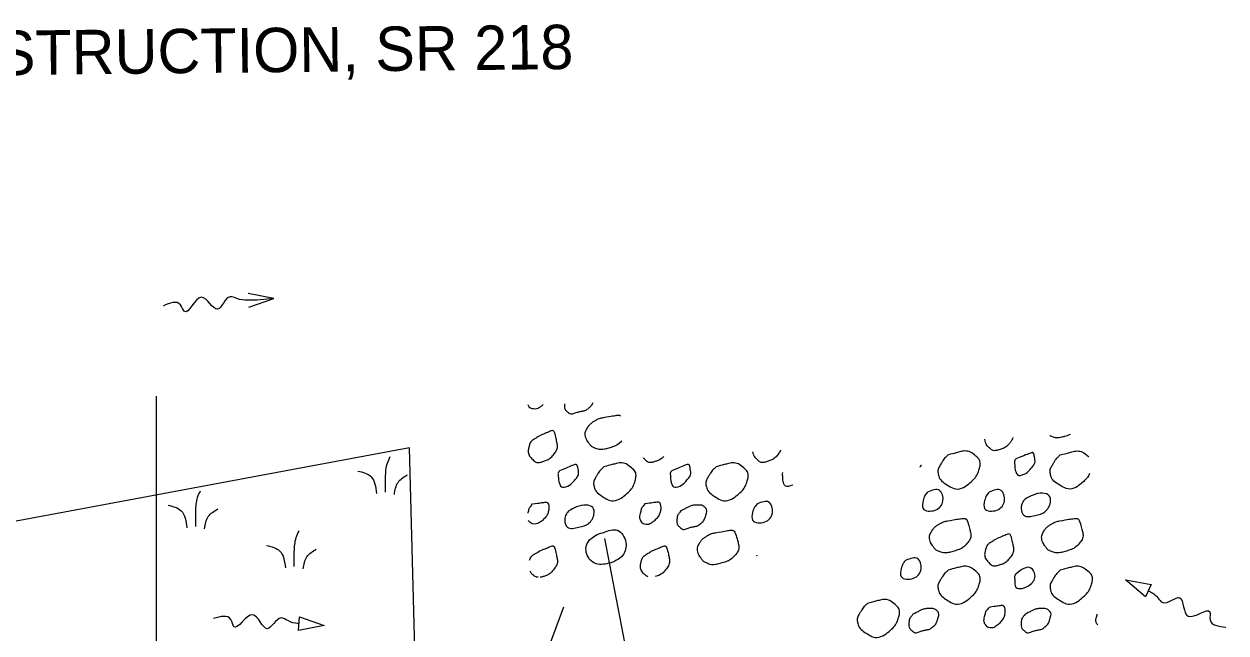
# Model space of a CAD drawing. Extents: x 0 to 3369, y -440 to 440.
# Drawn here: x 466.9 to 542.6, y 270.9 to 309.3 of the extents above; entities that cross this region are included whole.
import ezdxf

# ---------------------------------------------------------------- set-up
doc = ezdxf.new("R2010")
doc.units = 0
for name, color, linetype in [('GE_P_Alignment', 7, 'Continuous'), ('GE_P_Alignment_100_Stations', 7, 'Continuous'), ('MT_P_Work_Area', 7, 'Continuous'), ('PF_P_Grade_Line', 7, 'Continuous'), ('PV_P_EOP', 7, 'Continuous'), ('PV_P_Shoulder', 7, 'Continuous')]:
    doc.layers.add(name, color=color, linetype=linetype)

msp = doc.modelspace()

# ---------------------------------------------------------------- linework, layer by layer
at = {"layer": 'GE_P_Alignment'}
for points, degree in [([(499.586, 285.35), (499.531, 285.297), (499.473, 285.247), (499.415, 285.202), (499.205, 285.042), (498.763, 285.069), (498.642, 285.316), (498.641, 285.316), (498.641, 285.317), (498.641, 285.318)], 3), ([(502.709, 285.462), (502.654, 285.334), (502.575, 285.211), (502.448, 285.106), (502.248, 284.94), (502.037, 284.916), (501.822, 284.866), (501.596, 284.813), (501.339, 284.68), (501.118, 284.877), (500.973, 285.008), (500.943, 285.16), (500.947, 285.309), (500.948, 285.338), (500.949, 285.367), (500.951, 285.398)], 3), ([(504.541, 283.036), (504.291, 282.79), (504.016, 282.687), (503.713, 282.597), (503.431, 282.514), (503.115, 282.484), (502.833, 282.602), (502.663, 282.674), (502.539, 282.799), (502.435, 282.959), (502.262, 283.227), (502.211, 283.596), (502.362, 283.849), (502.462, 284.017), (502.598, 284.165), (502.772, 284.276), (502.919, 284.37), (503.06, 284.458), (503.223, 284.492), (503.278, 284.504), (503.333, 284.516), (503.388, 284.527)], 3), ([(503.372, 284.524), (503.674, 284.576), (503.977, 284.634), (504.28, 284.676), (504.345, 284.685), (504.403, 284.668), (504.454, 284.633)], 3), ([(499.332, 283.359), (499.566, 283.46), (499.801, 283.56), (500.035, 283.661), (500.278, 283.765), (500.397, 283.232), (500.45, 282.984), (500.507, 282.722), (500.439, 282.428), (500.227, 282.174), (500.027, 281.935), (499.8, 281.822), (499.56, 281.749), (499.368, 281.691), (499.126, 281.682), (498.938, 281.867), (498.711, 282.092), (498.626, 282.357), (498.672, 282.586), (498.708, 282.768), (498.793, 283.008), (498.963, 283.121), (499.086, 283.202), (499.209, 283.279), (499.332, 283.359)], 3), ([(532.818, 283.458), (532.71, 283.413), (532.598, 283.376), (532.482, 283.342), (532.199, 283.259), (531.883, 283.229), (531.602, 283.347), (531.573, 283.359), (531.546, 283.373), (531.52, 283.388)], 3), ([(529.189, 283.261), (529.15, 283.143), (529.085, 283.027), (528.995, 282.919), (528.796, 282.68), (528.568, 282.566), (528.328, 282.494), (528.136, 282.436), (527.895, 282.426), (527.707, 282.612), (527.532, 282.785), (527.442, 282.98), (527.429, 283.165)], 3), ([(507.195, 282.063), (507.022, 281.898), (506.831, 281.809), (506.632, 281.749), (506.44, 281.691), (506.198, 281.682), (506.01, 281.867), (505.969, 281.908), (505.932, 281.95), (505.901, 281.993)], 3), ([(514.545, 282.464), (514.505, 282.364), (514.447, 282.267), (514.37, 282.174), (514.171, 281.935), (513.943, 281.822), (513.703, 281.749), (513.512, 281.691), (513.27, 281.682), (513.082, 281.867), (512.923, 282.024), (512.834, 282.2), (512.81, 282.369)], 3), ([(525.11, 282.166), (525.347, 282.229), (525.584, 282.291), (525.822, 282.352), (526.168, 282.442), (526.517, 282.379), (526.863, 282.089), (527.132, 281.864), (527.149, 281.532), (527.078, 281.284), (526.988, 280.971), (526.79, 280.673), (526.487, 280.414), (526.107, 280.089), (525.579, 279.962), (525.19, 280.192), (524.875, 280.379), (524.542, 280.659), (524.482, 280.989), (524.444, 281.195), (524.551, 281.434), (524.672, 281.626), (524.758, 281.762), (524.834, 281.901), (524.948, 282.011), (525.002, 282.062), (525.056, 282.114), (525.11, 282.166)], 3), ([(529.383, 281.914), (529.7, 282.042), (530.017, 282.178), (530.333, 282.299), (530.489, 282.358), (530.571, 282.011), (530.585, 281.862), (530.604, 281.663), (530.451, 281.455), (530.287, 281.257), (530.063, 280.989), (529.502, 280.794), (529.387, 281.089), (529.325, 281.246), (529.315, 281.407), (529.308, 281.569), (529.305, 281.649), (529.275, 281.739), (529.317, 281.811), (529.338, 281.847), (529.361, 281.879), (529.383, 281.914)], 3), ([(534.03, 280.987), (533.922, 280.783), (533.764, 280.59), (533.558, 280.414), (533.178, 280.089), (532.65, 279.962), (532.262, 280.192), (531.946, 280.379), (531.614, 280.659), (531.553, 280.989), (531.515, 281.195), (531.622, 281.434), (531.743, 281.626), (531.829, 281.762), (531.906, 281.901), (532.02, 282.011), (532.074, 282.062), (532.127, 282.114), (532.182, 282.166)], 3), ([(532.182, 282.166), (532.419, 282.229), (532.656, 282.291), (532.893, 282.352), (533.24, 282.442), (533.588, 282.379), (533.935, 282.089), (533.948, 282.078), (533.96, 282.067), (533.971, 282.056)], 3), ([(500.615, 281.169), (500.932, 281.297), (501.248, 281.434), (501.565, 281.554), (501.721, 281.613), (501.803, 281.266), (501.817, 281.117), (501.836, 280.918), (501.683, 280.71), (501.518, 280.512), (501.295, 280.244), (500.734, 280.049), (500.618, 280.344), (500.557, 280.501), (500.547, 280.662), (500.54, 280.824), (500.537, 280.905), (500.507, 280.994), (500.548, 281.066), (500.57, 281.102), (500.593, 281.134), (500.615, 281.169)], 3), ([(503.413, 281.421), (503.65, 281.484), (503.888, 281.546), (504.125, 281.607), (504.472, 281.697), (504.82, 281.634), (505.167, 281.344), (505.435, 281.12), (505.453, 280.787), (505.382, 280.539), (505.292, 280.226), (505.094, 279.929), (504.79, 279.669), (504.41, 279.345), (503.882, 279.217), (503.493, 279.447), (503.178, 279.634), (502.846, 279.914), (502.785, 280.244), (502.747, 280.45), (502.854, 280.689), (502.975, 280.881), (503.061, 281.018), (503.138, 281.156), (503.252, 281.266), (503.306, 281.318), (503.359, 281.369), (503.413, 281.421)], 3), ([(507.687, 281.169), (508.003, 281.297), (508.32, 281.434), (508.637, 281.554), (508.792, 281.613), (508.874, 281.266), (508.888, 281.117), (508.907, 280.918), (508.754, 280.71), (508.59, 280.512), (508.367, 280.244), (507.806, 280.049), (507.69, 280.344), (507.629, 280.501), (507.618, 280.662), (507.612, 280.824), (507.608, 280.905), (507.578, 280.994), (507.62, 281.066), (507.641, 281.102), (507.665, 281.134), (507.687, 281.169)], 3), ([(510.485, 281.421), (510.722, 281.484), (510.96, 281.546), (511.197, 281.607), (511.543, 281.697), (511.892, 281.634), (512.238, 281.344), (512.507, 281.12), (512.525, 280.787), (512.453, 280.539), (512.364, 280.226), (512.166, 279.929), (511.862, 279.669), (511.482, 279.345), (510.954, 279.217), (510.565, 279.447), (510.25, 279.634), (509.918, 279.914), (509.857, 280.244), (509.819, 280.45), (509.926, 280.689), (510.047, 280.881), (510.133, 281.018), (510.21, 281.156), (510.323, 281.266), (510.377, 281.318), (510.431, 281.369), (510.485, 281.421)], 3), ([(523.415, 281.528), (523.388, 281.483), (523.358, 281.439), (523.325, 281.395)], 2), ([(515.318, 280.267), (515.087, 280.167), (514.835, 280.157), (514.762, 280.344), (514.7, 280.501), (514.69, 280.662), (514.683, 280.824), (514.68, 280.9), (514.654, 280.983), (514.685, 281.052)], 3), ([(498.635, 278.501), (498.639, 278.516), (498.643, 278.532), (498.647, 278.547), (498.677, 278.656), (498.692, 278.782), (498.763, 278.873), (498.817, 278.941), (498.87, 279.008), (498.923, 279.075)], 3), ([(498.923, 279.075), (499.178, 279.112), (499.432, 279.152), (499.687, 279.187), (499.914, 279.217), (499.967, 278.726), (499.895, 278.53), (499.816, 278.313), (499.619, 278.097), (499.415, 277.942), (499.21, 277.784), (498.782, 277.807), (498.65, 278.039)], 3), ([(505.995, 279.075), (506.25, 279.112), (506.504, 279.152), (506.758, 279.187), (506.986, 279.217), (507.039, 278.726), (506.967, 278.53), (506.888, 278.313), (506.69, 278.097), (506.487, 277.942), (506.277, 277.781), (505.835, 277.808), (505.713, 278.055), (505.637, 278.21), (505.675, 278.391), (505.718, 278.547), (505.749, 278.656), (505.763, 278.782), (505.835, 278.873), (505.888, 278.941), (505.942, 279.008), (505.995, 279.075)], 3), ([(508.27, 278.642), (508.437, 278.725), (508.603, 278.808), (508.77, 278.892), (508.953, 278.983), (509.172, 279.001), (509.372, 279.007), (509.519, 279.011), (509.661, 278.976), (509.793, 278.845), (509.915, 278.725), (509.897, 278.565), (509.862, 278.438), (509.803, 278.228), (509.724, 278.015), (509.52, 277.845), (509.32, 277.679), (509.108, 277.655), (508.893, 277.605), (508.668, 277.552), (508.41, 277.419), (508.19, 277.617), (508.045, 277.747), (508.014, 277.899), (508.018, 278.048), (508.022, 278.181), (508.038, 278.337), (508.122, 278.448), (508.171, 278.514), (508.22, 278.577), (508.27, 278.642)], 3), ([(525.068, 278.008), (525.371, 278.06), (525.674, 278.117), (525.977, 278.16), (526.279, 278.202), (526.419, 277.683), (526.495, 277.4), (526.564, 277.142), (526.519, 276.827), (526.302, 276.586), (526.035, 276.291), (525.739, 276.178), (525.41, 276.081), (525.127, 275.998), (524.811, 275.968), (524.53, 276.086), (524.359, 276.158), (524.235, 276.283), (524.132, 276.443), (523.959, 276.711), (523.907, 277.08), (524.058, 277.333), (524.158, 277.501), (524.294, 277.649), (524.468, 277.76), (524.616, 277.853), (524.757, 277.942), (524.92, 277.976), (524.975, 277.988), (525.03, 278), (525.085, 278.011)], 3), ([(532.14, 278.008), (532.442, 278.06), (532.746, 278.117), (533.048, 278.16), (533.351, 278.202), (533.491, 277.683), (533.567, 277.4), (533.635, 277.142), (533.591, 276.827), (533.373, 276.586), (533.107, 276.291), (532.81, 276.178), (532.482, 276.081), (532.199, 275.998), (531.883, 275.968), (531.602, 276.086), (531.431, 276.158), (531.307, 276.283), (531.203, 276.443), (531.03, 276.711), (530.979, 277.08), (531.13, 277.333), (531.23, 277.501), (531.366, 277.649), (531.54, 277.76), (531.687, 277.853), (531.828, 277.942), (531.992, 277.976), (532.047, 277.988), (532.102, 278), (532.157, 278.011)], 3), ([(510.443, 277.263), (510.746, 277.315), (511.049, 277.373), (511.352, 277.415), (511.654, 277.457), (511.794, 276.938), (511.87, 276.655), (511.939, 276.397), (511.894, 276.082), (511.677, 275.842), (511.41, 275.546), (511.114, 275.433), (510.785, 275.337), (510.503, 275.253), (510.186, 275.223), (509.905, 275.342), (509.734, 275.413), (509.61, 275.538), (509.507, 275.698), (509.334, 275.966), (509.282, 276.335), (509.433, 276.588), (509.533, 276.756), (509.669, 276.904), (509.843, 277.015), (509.991, 277.109), (510.132, 277.197), (510.295, 277.232), (510.35, 277.243), (510.405, 277.255), (510.46, 277.267)], 3), ([(528.1, 276.843), (528.334, 276.943), (528.569, 277.044), (528.803, 277.145), (529.046, 277.249), (529.165, 276.715), (529.218, 276.468), (529.275, 276.206), (529.207, 275.912), (528.995, 275.658), (528.796, 275.419), (528.568, 275.305), (528.328, 275.233), (528.136, 275.175), (527.895, 275.166), (527.707, 275.351), (527.479, 275.576), (527.394, 275.841), (527.44, 276.07), (527.476, 276.252), (527.561, 276.491), (527.732, 276.605), (527.854, 276.686), (527.977, 276.763), (528.1, 276.843)], 3), ([(498.733, 275.539), (498.782, 275.665), (498.855, 275.788), (498.963, 275.86), (499.086, 275.941), (499.209, 276.018), (499.332, 276.098)], 3), ([(499.332, 276.098), (499.566, 276.199), (499.801, 276.299), (500.035, 276.4), (500.278, 276.504), (500.397, 275.971), (500.45, 275.723), (500.507, 275.461), (500.439, 275.167), (500.227, 274.913), (500.027, 274.674), (499.8, 274.561), (499.56, 274.488), (499.506, 274.472), (499.448, 274.459), (499.389, 274.454)], 3), ([(506.185, 274.49), (506.124, 274.515), (506.065, 274.553), (506.01, 274.607), (505.783, 274.831), (505.698, 275.096), (505.743, 275.325), (505.78, 275.507), (505.865, 275.747), (506.035, 275.86), (506.158, 275.941), (506.281, 276.018), (506.403, 276.098)], 3), ([(506.403, 276.098), (506.638, 276.199), (506.872, 276.299), (507.107, 276.4), (507.35, 276.504), (507.468, 275.971), (507.522, 275.723), (507.578, 275.461), (507.51, 275.167), (507.298, 274.913), (507.103, 274.679), (506.881, 274.566), (506.647, 274.493)], 3), ([(513.045, 275.81), (513.057, 275.821), (513.069, 275.832), (513.082, 275.842)], 2), ([(525.11, 274.905), (525.347, 274.968), (525.584, 275.03), (525.822, 275.091), (526.168, 275.181), (526.517, 275.118), (526.863, 274.828), (527.132, 274.603), (527.149, 274.271), (527.078, 274.023), (526.988, 273.71), (526.79, 273.412), (526.487, 273.153), (526.107, 272.828), (525.579, 272.701), (525.19, 272.931), (524.875, 273.118), (524.542, 273.398), (524.482, 273.728), (524.444, 273.934), (524.551, 274.173), (524.672, 274.365), (524.758, 274.501), (524.834, 274.64), (524.948, 274.75), (525.002, 274.802), (525.056, 274.853), (525.11, 274.905)], 3), ([(532.182, 274.905), (532.419, 274.968), (532.656, 275.03), (532.893, 275.091), (533.24, 275.181), (533.588, 275.118), (533.935, 274.828), (534.204, 274.603), (534.221, 274.271), (534.15, 274.023), (534.06, 273.71), (533.862, 273.412), (533.558, 273.153), (533.178, 272.828), (532.65, 272.701), (532.262, 272.931), (531.946, 273.118), (531.614, 273.398), (531.553, 273.728), (531.515, 273.934), (531.622, 274.173), (531.743, 274.365), (531.829, 274.501), (531.906, 274.64), (532.02, 274.75), (532.074, 274.802), (532.127, 274.853), (532.182, 274.905)], 3), ([(499.272, 274.453), (499.156, 274.463), (499.039, 274.507), (498.938, 274.607), (498.861, 274.683), (498.801, 274.763), (498.756, 274.846)], 3), ([(520.025, 272.807), (520.262, 272.871), (520.5, 272.933), (520.737, 272.994), (521.083, 273.084), (521.432, 273.02), (521.779, 272.731), (522.047, 272.506), (522.065, 272.174), (521.994, 271.926), (521.904, 271.612), (521.706, 271.315), (521.402, 271.056), (521.022, 270.731), (520.494, 270.604), (520.105, 270.834), (519.79, 271.021), (519.458, 271.301), (519.397, 271.631), (519.359, 271.837), (519.466, 272.076), (519.587, 272.267), (519.673, 272.404), (519.75, 272.543), (519.864, 272.652), (519.917, 272.704), (519.971, 272.756), (520.025, 272.807)], 3), ([(522.895, 272.125), (523.061, 272.209), (523.228, 272.292), (523.395, 272.375), (523.578, 272.466), (523.797, 272.485), (523.997, 272.49), (524.144, 272.495), (524.286, 272.46), (524.418, 272.329), (524.539, 272.209), (524.522, 272.048), (524.487, 271.922), (524.428, 271.712), (524.349, 271.498), (524.145, 271.329), (523.945, 271.162), (523.733, 271.139), (523.518, 271.089), (523.293, 271.036), (523.035, 270.903), (522.815, 271.1), (522.669, 271.231), (522.639, 271.383), (522.643, 271.532), (522.647, 271.664), (522.663, 271.821), (522.747, 271.932), (522.796, 271.997), (522.845, 272.061), (522.895, 272.125)], 3), ([(527.692, 272.559), (527.946, 272.595), (528.201, 272.636), (528.455, 272.67), (528.682, 272.701), (528.735, 272.21), (528.663, 272.014), (528.584, 271.797), (528.387, 271.581), (528.183, 271.425), (527.974, 271.265), (527.532, 271.291), (527.41, 271.539), (527.333, 271.694), (527.372, 271.874), (527.415, 272.03), (527.445, 272.14), (527.46, 272.266), (527.532, 272.357), (527.585, 272.424), (527.638, 272.491), (527.692, 272.559)], 3), ([(529.967, 272.125), (530.133, 272.209), (530.299, 272.292), (530.467, 272.375), (530.65, 272.466), (530.869, 272.485), (531.068, 272.49), (531.215, 272.495), (531.357, 272.46), (531.49, 272.329), (531.611, 272.209), (531.594, 272.048), (531.558, 271.922), (531.499, 271.712), (531.421, 271.498), (531.217, 271.329), (531.016, 271.162), (530.805, 271.139), (530.59, 271.089), (530.365, 271.036), (530.107, 270.903), (529.887, 271.1), (529.741, 271.231), (529.711, 271.383), (529.715, 271.532), (529.718, 271.664), (529.735, 271.821), (529.818, 271.932), (529.868, 271.997), (529.917, 272.061), (529.967, 272.125)], 3), ([(534.549, 271.449), (534.521, 271.475), (534.498, 271.505), (534.482, 271.539), (534.405, 271.694), (534.443, 271.874), (534.487, 272.03), (534.496, 272.063), (534.503, 272.098), (534.512, 272.132)], 3)]:
    msp.add_open_spline(points, degree=degree, dxfattribs=at)
for points in [[(523.814, 279.82), (524.577, 279.931), (524.785, 279.275), (524.305, 278.686), (523.532, 278.8), (523.537, 279.291), (523.654, 279.618), (523.814, 279.82)], [(527.692, 279.82), (528.455, 279.931), (528.663, 279.275), (528.183, 278.686), (527.41, 278.8), (527.415, 279.291), (527.532, 279.618), (527.692, 279.82)], [(529.967, 279.386), (530.467, 279.636), (531.068, 279.751), (531.49, 279.59), (531.558, 279.183), (531.217, 278.59), (530.59, 278.35), (529.887, 278.361), (529.715, 278.793), (529.818, 279.193), (529.967, 279.386)], [(501.198, 278.642), (501.698, 278.892), (502.3, 279.007), (502.722, 278.845), (502.79, 278.438), (502.448, 277.845), (501.822, 277.605), (501.118, 277.617), (500.947, 278.048), (501.05, 278.448), (501.198, 278.642)], [(513.067, 279.075), (513.83, 279.187), (514.038, 278.53), (513.558, 277.942), (512.785, 278.055), (512.79, 278.547), (512.907, 278.873), (513.067, 279.075)], [(503.372, 277.263), (504.28, 277.415), (504.798, 276.655), (504.605, 275.842), (503.713, 275.337), (502.833, 275.342), (502.435, 275.698), (502.362, 276.588), (502.772, 277.015), (503.223, 277.232), (503.388, 277.267)], [(522.436, 275.522), (523.199, 275.633), (523.407, 274.977), (522.927, 274.388), (522.154, 274.502), (522.159, 274.993), (522.276, 275.32), (522.436, 275.522)], [(529.383, 274.653), (530.333, 275.038), (530.585, 274.601), (530.287, 273.996), (529.387, 273.828), (529.308, 274.308), (529.317, 274.55), (529.383, 274.653)]]:
    msp.add_spline(points, degree=3, dxfattribs=at)
at = {"layer": 'GE_P_Alignment_100_Stations'}
msp.add_lwpolyline([(448.999, 249.632), (491.761, 259.625), (491.153, 282.617), (448.315, 274.622)], close=True, dxfattribs=at)
at = {"layer": 'MT_P_Work_Area'}
for p, q in [((482.61, 292.023), (480.985, 292.344)), ((481.043, 291.488), (482.61, 292.023))]:
    msp.add_line(p, q, dxfattribs=at)
msp.add_spline([(482.61, 292.023), (480.952, 291.916), (480.285, 292.021), (479.86, 292.138), (479.063, 291.347), (478.039, 292.105), (476.977, 291.207), (476.721, 291.637), (475.626, 291.551)], degree=3, dxfattribs=at)
at = {"layer": 'PF_P_Grade_Line'}
for points in [[(489.652, 279.814), (489.652, 280.76), (489.77, 281.649), (489.947, 282.064)], [(487.905, 281.154), (488.734, 280.8), (489.089, 279.734)], [(490.207, 279.67), (490.444, 280.439), (491.034, 280.914)], [(477.689, 277.66), (477.689, 278.607), (477.808, 279.495), (477.984, 279.91)], [(475.943, 279), (476.771, 278.647), (477.126, 277.58)], [(478.244, 277.517), (478.481, 278.285), (479.071, 278.76)], [(483.902, 275.123), (483.902, 276.069), (484.021, 276.958), (484.197, 277.373)], [(482.156, 276.463), (482.984, 276.109), (483.339, 275.043)], [(484.457, 274.979), (484.694, 275.748), (485.284, 276.223)]]:
    msp.add_spline(points, degree=3, dxfattribs=at)
at = {"layer": 'PV_P_EOP'}
for p, q in [((475.187, 285.868), (475.187, 247.041)), ((509.251, 246.944), (503.482, 276.905)), ((491.158, 246.697), (500.894, 272.595))]:
    msp.add_line(p, q, dxfattribs=at)
at = {"layer": 'PV_P_Shoulder'}
for p, q in [((537.553, 273.224), (536.288, 274.293)), ((536.288, 274.293), (537.918, 274.001)), ((537.918, 274.001), (537.553, 273.224)), ((484.168, 271.095), (484.22, 271.951)), ((485.791, 271.424), (484.168, 271.095)), ((484.22, 271.951), (485.791, 271.424))]:
    msp.add_line(p, q, dxfattribs=at)
for points in [[(537.733, 273.609), (537.79, 273.582), (538.322, 273.167), (538.638, 272.859), (539.718, 273.164), (540.246, 272.005), (541.61, 272.276), (541.625, 271.775), (542.625, 271.319)], [(484.196, 271.527), (484.133, 271.531), (483.485, 271.721), (483.078, 271.891), (482.186, 271.209), (481.268, 272.092), (480.1, 271.337), (479.901, 271.797), (478.804, 271.852)]]:
    msp.add_spline(points, degree=3, dxfattribs=at)

# ---------------------------------------------------------------- texts
at = {"layer": 'PV_P_EOP'}
msp.add_text(' CONSTRUCTION, SR 218', height=2.8, rotation=0.61714, dxfattribs=at).set_placement((455.737, 306.006))

doc.saveas('drawing.dxf')
